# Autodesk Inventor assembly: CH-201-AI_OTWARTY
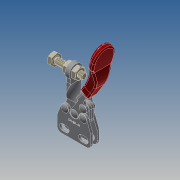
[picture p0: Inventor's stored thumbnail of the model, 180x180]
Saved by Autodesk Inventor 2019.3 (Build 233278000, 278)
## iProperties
Company: Î¢ÈíÖÐ¹ú
Created: 2012-09
Part Number: CH-201-AI_OTWARTY
Material: Ogólny
Description: STEP AP203
Document SubType Name: Assembly
Designer: CADENGINEERING4
Sending System: SolidWorks 2010
Preprocessor: SwSTEP 2.0
Title: CH-201-AI.STEP
Author: Î¢ÈíÓÃ»§
Revision Number: ÈÎºÎ
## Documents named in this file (8)
- E:\STRONA\Horizontal toggle clamp\CH-201-AI\CH-201-AI_OTWARTY.iam
- E:\STRONA\Horizontal toggle clamp\CH-201-AI\CH-201-A-04.ipt
- E:\STRONA\Horizontal toggle clamp\CH-201-AI\CH-201-A-02 SOLID BAR.ipt
- E:\STRONA\Horizontal toggle clamp\CH-201-AI\CH-SA-042007 SPINDLE SUPPLIED.ipt
- E:\STRONA\Horizontal toggle clamp\CH-201-AI\CH-201-A-06.ipt
- E:\STRONA\Horizontal toggle clamp\CH-201-AI\CH-201-03 HANDLE.iam
- E:\STRONA\Horizontal toggle clamp\CH-201-AI\M4 Nut.ipt
- E:\STRONA\Horizontal toggle clamp\CH-201-AI\CH-201-AI-01 FLANGED BASE.ipt
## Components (12 placed, 12 different names)
1. CH-201-A-04_1 — Zestawiające:5, Zestawiające:6, Zestawiające:7
2. CH-201-A-02 SOLID BAR_2 — Równoległe:1, Zestawiające:14, Zestawiające:17, Zestawiające:18, Zestawiające:19, Zestawiające:20, Zestawiające:21, Zestawiające:22
3. CH-SA-042007 SPINDLE SUPPLIED_3 — Równoległe:1, Zestawiające:14, Zestawiające:15, Zestawiające:16
4. CH-201-A-06_4 — Zestawiające:8, Zestawiające:9, Zestawiające:10
5. CH-201-A-04_5 — Zestawiające:5, Zestawiające:6, Zestawiające:7, Zestawiające:10, Zestawiające:11, Zestawiające:12, Zestawiające:13
6. CH-201-03 HANDLE_6 [sub-assembly] — Zestawiające:1, Zestawiające:2, Zestawiające:3, Zestawiające:4, Zestawiające:12, Przejściowe:1
7. CH-201-A-06_7 — Zestawiające:2, Zestawiające:3, Zestawiające:21
8. CH-201-A-06_8 — Zestawiające:1, Zestawiające:4, Zestawiające:13
9. M4 Nut_9 — Zestawiające:16, Zestawiające:17
10. M4 Nut_10 — Zestawiające:15, Zestawiające:18
11. CH-201-AI-01 FLANGED BASE_11 — Zestawiające:8, Zestawiające:9, Zestawiające:11, Zestawiające:19, Zestawiające:22, Zestawiające:23, Przejściowe:1
12. CH-201-A-06_12 — Zestawiające:20, Zestawiające:23
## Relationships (25: Mate 23, Flush 1, Transitional 1)
- Zestawiające:1 [Mate]: CH-201-03 HANDLE_6 ↔ CH-201-A-06_8
- Zestawiające:2 [Mate]: CH-201-03 HANDLE_6 ↔ CH-201-A-06_7
- Zestawiające:3 [Mate]: CH-201-03 HANDLE_6 ↔ CH-201-A-06_7
- Zestawiające:4 [Mate]: CH-201-03 HANDLE_6 ↔ CH-201-A-06_8
- Zestawiające:5 [Mate]: CH-201-A-04_1 ↔ CH-201-A-04_5
- Zestawiające:6 [Mate]: CH-201-A-04_1 ↔ CH-201-A-04_5
- Zestawiające:7 [Mate]: CH-201-A-04_1 ↔ CH-201-A-04_5
- Zestawiające:8 [Mate]: CH-201-A-06_4 ↔ CH-201-AI-01 FLANGED BASE_11
- Zestawiające:9 [Mate]: CH-201-A-06_4 ↔ CH-201-AI-01 FLANGED BASE_11
- Zestawiające:10 [Mate]: CH-201-A-06_4 ↔ CH-201-A-04_5
- Zestawiające:11 [Mate]: CH-201-A-04_5 ↔ CH-201-AI-01 FLANGED BASE_11
- Zestawiające:12 [Mate]: CH-201-A-04_5 ↔ CH-201-03 HANDLE_6
- Zestawiające:13 [Mate]: CH-201-A-04_5 ↔ CH-201-A-06_8
- Równoległe:1 [Flush]: CH-201-A-02 SOLID BAR_2 ↔ CH-SA-042007 SPINDLE SUPPLIED_3
- Zestawiające:14 [Mate]: CH-201-A-02 SOLID BAR_2 ↔ CH-SA-042007 SPINDLE SUPPLIED_3
- Zestawiające:15 [Mate]: CH-SA-042007 SPINDLE SUPPLIED_3 ↔ M4 Nut_10
- Zestawiające:16 [Mate]: CH-SA-042007 SPINDLE SUPPLIED_3 ↔ M4 Nut_9
- Zestawiające:17 [Mate]: CH-201-A-02 SOLID BAR_2 ↔ M4 Nut_9
- Zestawiające:18 [Mate]: CH-201-A-02 SOLID BAR_2 ↔ M4 Nut_10
- Zestawiające:19 [Mate]: CH-201-A-02 SOLID BAR_2 ↔ CH-201-AI-01 FLANGED BASE_11
- Zestawiające:20 [Mate]: CH-201-A-02 SOLID BAR_2 ↔ CH-201-A-06_12
- Zestawiające:21 [Mate]: CH-201-A-02 SOLID BAR_2 ↔ CH-201-A-06_7
- Zestawiające:22 [Mate]: CH-201-A-02 SOLID BAR_2 ↔ CH-201-AI-01 FLANGED BASE_11
- Zestawiające:23 [Mate]: CH-201-AI-01 FLANGED BASE_11 ↔ CH-201-A-06_12
- Przejściowe:1 [Transitional]: CH-201-03 HANDLE_6 ↔ CH-201-AI-01 FLANGED BASE_11
